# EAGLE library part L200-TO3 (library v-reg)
VOLTAGE REGULATOR
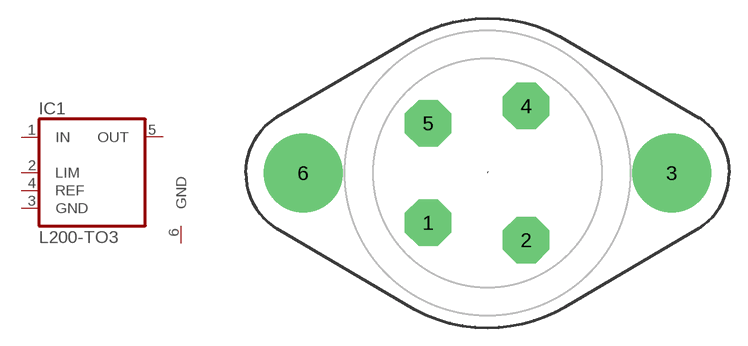
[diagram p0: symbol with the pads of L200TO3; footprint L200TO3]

Designator prefix IC; gates 1=L200 G$1=GND

## L200-TO3  [L200TO3]
1  1:IN  in
2  1:LIM  in
3  1:GND  pas
4  1:REF  in
5  1:OUT  pas
6  G$1:GND  pwr

## Footprint L200TO3 (pad centres in mm)
VOLTAGE REGULATOR L200.pdf from www.st.com
drill 1.194 pad 3.81 octagon: 1 -4.864,-4.082; 2 3.175,-5.499; 4 3.175,5.499; 5 -4.864,4.082
drill 4.115 pad 6.477 round: 3 15.113,0; 6 -15.113,0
